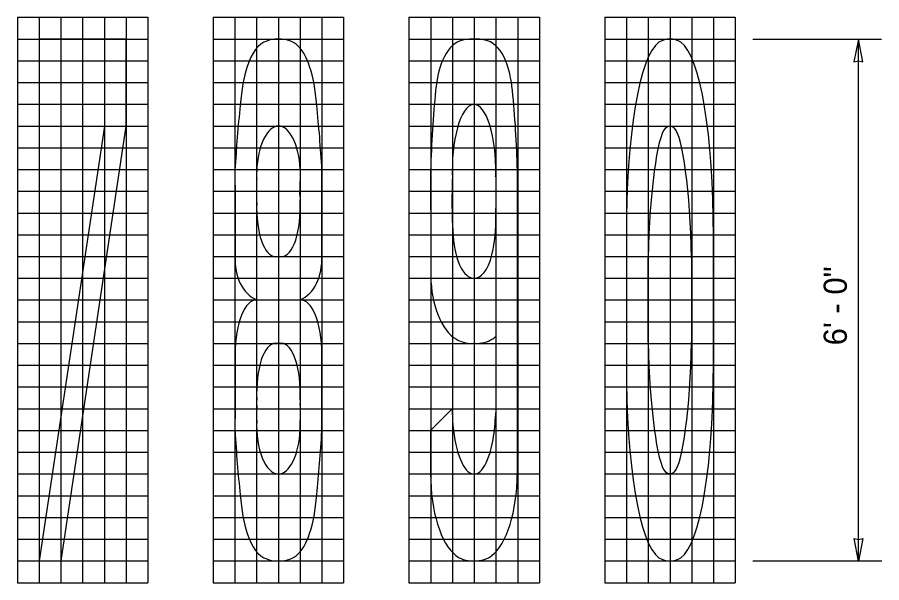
# Model space of a CAD drawing. Extents: x 99862 to 103151, y 100000 to 102076.
# Drawn here: x 101855 to 102451, y 101067 to 101457 of the extents above; entities that cross this region are included whole.
import ezdxf

# ---------------------------------------------------------------- set-up
doc = ezdxf.new("R2010")
doc.units = 0
for name, color, linetype in [('Level 15', 7, 'Continuous'), ('Level 20', 7, 'Continuous'), ('Level 4', 7, 'Continuous')]:
    doc.layers.add(name, color=color, linetype=linetype)

msp = doc.modelspace()

# ---------------------------------------------------------------- linework, layer by layer
at = {"layer": 'Level 15'}
for p, q in [((102362.5, 101442.28), (102451.43, 101442.28)), ((102435.43, 101082.28), (102435.43, 101442.28)), ((102362.5, 101082.28), (102451.46, 101082.28))]:
    msp.add_line(p, q, dxfattribs=at)
for points in [[(102435.43, 101442.28), (102432.35, 101426.55), (102435.43, 101427.28), (102438.52, 101426.55)], [(102435.46, 101082.12), (102432.38, 101097.85), (102435.46, 101097.12), (102438.55, 101097.85)]]:
    msp.add_lwpolyline(points, close=True, dxfattribs=at)
at = {"layer": 'Level 20'}
for p, q in [((102005.46, 101351.81), (102005.5, 101331.29)), ((102050.46, 101352.28), (102050.46, 101344.31)), ((102065.43, 101331.29), (102065.46, 101351.81)), ((102140.36, 101348.93), (102140.45, 101299.33)), ((102200.24, 101299.3), (102200.33, 101348.91)), ((102020.46, 101331.29), (102020.46, 101345.72)), ((102155.35, 101325.6), (102155.43, 101345.79)), ((102185.25, 101347.34), (102185.34, 101325.57)), ((102005.5, 101331.29), (102005.5, 101293.05)), ((102020.46, 101330.28), (102020.46, 101331.29)), ((102050.22, 101335.02), (102050.43, 101331.29)), ((102065.43, 101293.05), (102065.43, 101331.29)), ((102020.44, 101329.48), (102020.46, 101330.28)), ((102275.41, 101306.34), (102275.41, 101262.28)), ((102335.39, 101262.28), (102335.39, 101306.34)), ((102140.45, 101299.33), (102140.45, 101278.91)), ((102200.24, 101294.14), (102200.24, 101299.3)), ((102037.47, 101292.12), (102033.46, 101292.12)), ((102200.3, 101184.46), (102200.3, 101294.14)), ((102290.4, 101262.28), (102290.4, 101291.34)), ((102320.4, 101291.34), (102320.4, 101262.28)), ((102140.45, 101278.91), (102140.54, 101278.91)), ((102275.41, 101262.28), (102275.41, 101218.22)), ((102290.4, 101233.22), (102290.4, 101262.28)), ((102320.4, 101262.28), (102320.4, 101233.22)), ((102335.39, 101218.22), (102335.39, 101262.28)), ((102185.31, 101237.11), (102185.31, 101184.46)), ((102033.52, 101232.43), (102037.41, 101232.43)), ((102169.57, 101232.28), (102170.34, 101232.25)), ((102005.5, 101224.97), (102005.5, 101188.14)), ((102065.43, 101188.14), (102065.43, 101224.97)), ((102005.5, 101188.14), (102005.46, 101172.75)), ((102020.55, 101189.65), (102020.54, 101193.26)), ((102050.39, 101193.26), (102050.41, 101190.82)), ((102050.46, 101189.69), (102050.46, 101179.31)), ((102065.46, 101172.75), (102065.43, 101188.14)), ((102155.4, 101187.55), (102140.33, 101172.24)), ((102155.39, 101182.98), (102155.4, 101187.55)), ((102200.21, 101142.25), (102200.3, 101184.46)), ((102140.33, 101172.24), (102140.33, 101142.25)), ((102200.12, 101142.25), (102200.21, 101142.25))]:
    msp.add_line(p, q, dxfattribs=at)
msp.add_lwpolyline([(101915.46, 101382.28), (101870.46, 101082.28), (101885.7, 101082.28), (101930.46, 101382.28), (101930.46, 101442.28), (101870.46, 101442.28), (101870.46, 101382.28)], close=True, dxfattribs=at)
for centre, major_axis, ratio, start_param, end_param in [((102066.79, 101259.75), (38.58, -181.34), 0.246365, 3.159715, 3.546722), ((102035.44, 101438.76), (10.08, 0), 0.348837, 0.665473, 2.491733), ((102004.14, 101259.75), (-38.58, -181.34), 0.246365, 2.736464, 3.126953), ((102201.49, 101299.74), (-40.06, 141.44), 0.306224, 0.010044, 0.37097), ((102168.95, 101439.49), (9.69, 0.05), 0.28716, 1.501343, 2.532224), ((102169.66, 101441.83), (1.56, 0.01), 0.28716, 1.115415, 1.600803), ((102171.73, 101439.47), (-9.69, 0.05), 0.28716, 3.750961, 4.857802), ((102139.2, 101299.72), (40.06, 141.44), 0.306224, 5.912215, 6.273141), ((102305.4, 101291.97), (3.75, -149.37), 0.19927, 3.270148, 4.611013), ((102297.9, 101126.7), (-7.85, -315.58), 0.19927, 3.02647, 3.266464), ((102305.41, 101292.04), (-3.72, -149.3), 0.19927, 1.671693, 3.012646), ((102161.46, 101371.64), (-5.85, 62.71), 0.27885, 0.460005, 0.951871), ((102179.23, 101371.62), (5.85, 62.71), 0.27885, 5.331315, 5.82318), ((102026.74, 101351.71), (5.67, -80.23), 0.218823, 3.612153, 4.104018), ((102044.18, 101351.71), (-5.67, -80.23), 0.218823, 2.179168, 2.671033), ((102219.18, 101269.61), (-18.14, 275.54), 0.279295, 1.03178, 1.251054), ((102121.51, 101269.59), (18.14, 275.54), 0.279295, 5.032131, 5.251405), ((102059.93, 101269.6), (4.68, -255.82), 0.218821, 4.189125, 4.381242), ((102011, 101269.6), (-4.68, -255.82), 0.218821, 1.901943, 2.09406), ((102170.31, 101351.32), (0, 45.93), 0.326391, 0.046211, 1.691605), ((102170.31, 101351.32), (0, 45.93), 0.326391, 0.017819, 0.046211), ((102170.31, 101351.32), (0, 45.93), 0.326391, 6.281207, 6.301005), ((102170.31, 101351.32), (0, 45.93), 0.326391, 4.6597, 6.281207), ((102035.18, 101349.01), (-0.3, -33.27), 0.443662, 3.159722, 4.650111), ((102035.45, 101340.56), (0, -41.72), 0.353933, 3.140679, 3.157785), ((102035.54, 101348.41), (0.06, -33.87), 0.443662, 1.684508, 3.142616), ((102301.42, 101291.09), (-2.11, -90.25), 0.122012, 3.268533, 4.71248), ((102299.43, 101121.68), (-6.09, -260.36), 0.122012, 3.042541, 3.248082), ((102309.39, 101291.09), (2.11, -90.25), 0.122012, 1.570705, 3.018849), ((102035.18, 101349.01), (-0.3, -33.27), 0.443662, 4.650111, 4.815474), ((102219.18, 101269.61), (-18.14, 275.54), 0.279295, 1.251054, 1.260463), ((102170.31, 101351.32), (0, 45.93), 0.326391, 4.625574, 4.6597), ((102121.51, 101269.59), (18.14, 275.54), 0.279295, 5.022722, 5.032131), ((102035.33, 101340.21), (-1.08, -42.68), 0.353933, 1.608151, 1.675965), ((102035.33, 101340.21), (-1.08, -42.68), 0.353933, 1.457775, 1.608151), ((102035.57, 101331.52), (2.12, -39.39), 0.375885, 6.268799, 7.827952), ((102035.36, 101331.52), (-2.12, -39.39), 0.375885, 4.784318, 6.297572), ((102160.18, 101320.84), (0, 29.96), 0.163293, 1.411316, 2.46776), ((102180.48, 101320.83), (0, 30.12), 0.163293, 3.821205, 4.870391), ((102170.31, 101310.08), (0, 32.81), 0.435527, 1.966446, 2.78592), ((102168.83, 101314.13), (-1.69, 36.88), 0.428388, 3.209517, 4.22215), ((102115.99, 101384.93), (-100.67, -119.36), 0.381725, 5.846217, 6.385455), ((101954.94, 101384.93), (100.67, -119.36), 0.381725, 6.180916, 6.720154), ((102165.73, 101279.3), (-0.06, 46.28), 0.544273, 1.578428, 2.834125), ((102170.31, 101310.08), (0, 32.81), 0.435527, 2.78592, 3.084732), ((102170.31, 101310.08), (0, 32.81), 0.435527, 3.084732, 3.124945), ((102170.31, 101310.08), (0, 32.81), 0.435527, 3.124945, 3.145709), ((102170.19, 101321.15), (0, 43.89), 0.435527, 3.151101, 3.215129), ((102020.28, 101223.77), (0.28, -38.53), 0.383378, 3.107477, 4.678273), ((102050.65, 101223.77), (-0.28, -38.53), 0.383378, 1.604912, 3.175708), ((102174.96, 101279.27), (0.06, 46.28), 0.544273, 3.44906, 3.567316), ((102035.39, 101193.04), (2.12, -39.39), 0.375885, 3.124969, 4.686367), ((102035.54, 101193.04), (-2.12, -39.39), 0.375885, 1.596818, 3.158216), ((102170.33, 101238.02), (-14.05, 0.04), 0.409613, 0.523879, 1.517527), ((102170.36, 101238), (14.05, 0.04), 0.409613, 4.710427, 5.759306), ((102301.42, 101233.47), (2.11, -90.25), 0.122012, 4.712298, 6.156245), ((102309.39, 101233.47), (-2.11, -90.25), 0.122012, 0.122744, 1.570888), ((102305.4, 101232.59), (-3.75, -149.37), 0.19927, 4.813765, 6.15463), ((102305.41, 101232.52), (3.72, -149.3), 0.19927, 0.128946, 1.4699), ((102035.48, 101183.88), (-0.25, -42.65), 0.353933, 4.597839, 4.832837), ((102035.48, 101183.88), (-0.25, -42.65), 0.353933, 4.58824, 4.597839), ((102035.48, 101183.88), (-0.25, -42.65), 0.353933, 4.578654, 4.58824), ((102035.48, 101183.88), (-0.25, -42.65), 0.353933, 1.709628, 1.736462), ((102170.31, 101187.24), (0, 45), 0.33319, 1.665564, 4.222129), ((102058.23, 101186.69), (16.39, 144.14), 0.87517, 4.668647, 4.789722), ((102058.23, 101186.69), (16.39, 144.14), 0.87517, 4.789722, 4.796182), ((102035.17, 101175.55), (0.29, -33.27), 0.443662, 4.609304, 6.265056), ((102035.82, 101175.43), (-0.36, -33.15), 0.443662, 1.497439, 1.693033), ((102059.37, 101253.65), (-4.57, -253.18), 0.218821, 5.041601, 5.044505), ((102059.37, 101253.65), (-4.57, -253.18), 0.218821, 5.044505, 5.235652), ((102035.82, 101175.43), (-0.36, -33.15), 0.443662, 6.282162, 7.780625), ((102011.56, 101253.65), (4.57, -253.18), 0.218821, 1.047533, 1.23868), ((102011.56, 101253.65), (4.57, -253.18), 0.218821, 1.23868, 1.241584), ((102035.44, 101184), (0, -41.72), 0.353933, 6.266993, 6.284099), ((102165.63, 101142.66), (0, 59.47), 0.42542, 1.577801, 2.825639), ((102174.93, 101142.74), (0.05, 59.5), 0.423324, 3.448728, 4.704425), ((102299.43, 101402.88), (6.09, -260.36), 0.122012, 6.176696, 6.382237), ((102026.74, 101172.84), (-5.67, -80.23), 0.218823, 5.32076, 5.812625), ((102044.18, 101172.84), (5.67, -80.23), 0.218823, 0.47056, 0.962425), ((102066.79, 101264.81), (-38.58, -181.34), 0.246365, 5.878056, 6.265063), ((102004.14, 101264.81), (38.58, -181.34), 0.246365, 0.014639, 0.405129), ((102035.44, 101085.79), (10.08, 0), 0.348837, 3.791452, 5.617712), ((102170.2, 101089.76), (14.21, 0), 0.526645, 3.647253, 5.759318), ((102297.9, 101397.86), (7.85, -315.58), 0.19927, 6.158314, 6.398307)]:
    msp.add_ellipse(centre, major_axis=major_axis, ratio=ratio, start_param=start_param, end_param=end_param, dxfattribs=at)
at = {"layer": 'Level 4'}
for p, q in [((101855.43, 101457.28), (101855.43, 101067.28)), ((101855.51, 101457.28), (101945.43, 101457.28)), ((101870.43, 101457.28), (101870.43, 101067.28)), ((101885.43, 101457.28), (101885.43, 101067.28)), ((101900.43, 101457.28), (101900.43, 101067.28)), ((101915.43, 101457.28), (101915.43, 101067.28)), ((101930.43, 101457.28), (101930.43, 101067.28)), ((101945.43, 101457.28), (101945.43, 101067.28)), ((101990.43, 101457.28), (101990.43, 101067.28)), ((101990.45, 101457.28), (102080.43, 101457.28)), ((102005.43, 101457.28), (102005.43, 101067.28)), ((102020.43, 101457.28), (102020.43, 101067.28)), ((102035.43, 101457.28), (102035.43, 101067.28)), ((102050.43, 101457.28), (102050.43, 101067.28)), ((102065.43, 101457.28), (102065.43, 101067.28)), ((102080.43, 101457.28), (102080.43, 101067.28)), ((102125.43, 101457.28), (102125.43, 101067.28)), ((102125.48, 101457.28), (102215.43, 101457.28)), ((102140.43, 101457.28), (102140.43, 101067.28)), ((102155.43, 101457.28), (102155.43, 101067.28)), ((102170.43, 101457.28), (102170.43, 101067.28)), ((102185.43, 101457.28), (102185.43, 101067.28)), ((102200.43, 101457.28), (102200.43, 101067.28)), ((102215.43, 101457.28), (102215.43, 101067.28)), ((102260.49, 101457.28), (102350.5, 101457.28)), ((102260.5, 101457.28), (102260.5, 101067.28)), ((102275.5, 101457.28), (102275.5, 101067.28)), ((102290.5, 101457.28), (102290.5, 101067.28)), ((102305.5, 101457.28), (102305.5, 101067.28)), ((102320.5, 101457.28), (102320.5, 101067.28)), ((102335.5, 101457.28), (102335.5, 101067.28)), ((102350.5, 101457.28), (102350.5, 101067.28)), ((101855.36, 101442.28), (101945.43, 101442.28)), ((101990.36, 101442.28), (102080.43, 101442.28)), ((102125.36, 101442.28), (102215.43, 101442.28)), ((102260.43, 101442.28), (102350.5, 101442.28)), ((101855.36, 101427.28), (101945.43, 101427.28)), ((101990.36, 101427.28), (102080.43, 101427.28)), ((102125.36, 101427.28), (102215.43, 101427.28)), ((102260.43, 101427.28), (102350.5, 101427.28)), ((101855.57, 101412.28), (101945.43, 101412.28)), ((101990.57, 101412.28), (102080.43, 101412.28)), ((102125.57, 101412.28), (102215.43, 101412.28)), ((102260.64, 101412.28), (102350.5, 101412.28)), ((101855.36, 101397.28), (101945.43, 101397.28)), ((101990.36, 101397.28), (102080.43, 101397.28)), ((102125.36, 101397.28), (102215.43, 101397.28)), ((102260.43, 101397.28), (102350.5, 101397.28)), ((101855.36, 101382.28), (101945.43, 101382.28)), ((101990.36, 101382.28), (102080.43, 101382.28)), ((102125.36, 101382.28), (102215.43, 101382.28)), ((102260.43, 101382.28), (102350.5, 101382.28)), ((101855.47, 101367.28), (101945.43, 101367.28)), ((101990.47, 101367.28), (102080.43, 101367.28)), ((102125.47, 101367.28), (102215.43, 101367.28)), ((102260.54, 101367.28), (102350.5, 101367.28)), ((101855.47, 101352.28), (101945.43, 101352.28)), ((101990.47, 101352.28), (102080.43, 101352.28)), ((102125.47, 101352.28), (102215.43, 101352.28)), ((102260.54, 101352.28), (102350.5, 101352.28)), ((101855.57, 101337.28), (101945.43, 101337.28)), ((101990.57, 101337.28), (102080.43, 101337.28)), ((102125.57, 101337.28), (102215.43, 101337.28)), ((102260.64, 101337.28), (102350.5, 101337.28)), ((101855.57, 101322.28), (101945.43, 101322.28)), ((101990.57, 101322.28), (102080.43, 101322.28)), ((102125.57, 101322.28), (102215.43, 101322.28)), ((102260.64, 101322.28), (102350.5, 101322.28)), ((101855.36, 101307.28), (101945.43, 101307.28)), ((101990.36, 101307.28), (102080.43, 101307.28)), ((102125.36, 101307.28), (102215.43, 101307.28)), ((102260.43, 101307.28), (102350.5, 101307.28)), ((101855.47, 101292.28), (101945.43, 101292.28)), ((101990.47, 101292.28), (102080.43, 101292.28)), ((102125.47, 101292.28), (102215.43, 101292.28)), ((102260.54, 101292.28), (102350.5, 101292.28)), ((101855.36, 101277.28), (101945.43, 101277.28)), ((101990.36, 101277.28), (102080.43, 101277.28)), ((102125.36, 101277.28), (102215.43, 101277.28)), ((102260.43, 101277.28), (102350.5, 101277.28)), ((101855.47, 101262.28), (101945.43, 101262.28)), ((101990.47, 101262.28), (102080.43, 101262.28)), ((102125.47, 101262.28), (102215.43, 101262.28)), ((102260.54, 101262.28), (102350.5, 101262.28)), ((101855.47, 101247.28), (101945.43, 101247.28)), ((101990.47, 101247.28), (102080.43, 101247.28)), ((102125.47, 101247.28), (102215.43, 101247.28)), ((102260.54, 101247.28), (102350.5, 101247.28)), ((101855.36, 101232.28), (101945.43, 101232.28)), ((101990.36, 101232.28), (102080.43, 101232.28)), ((102125.36, 101232.28), (102215.43, 101232.28)), ((102260.43, 101232.28), (102350.5, 101232.28)), ((101855.47, 101217.28), (101945.43, 101217.28)), ((101990.47, 101217.28), (102080.43, 101217.28)), ((102125.47, 101217.28), (102215.43, 101217.28)), ((102260.54, 101217.28), (102350.5, 101217.28)), ((101855.47, 101202.28), (101945.43, 101202.28)), ((101990.47, 101202.28), (102080.43, 101202.28)), ((102125.47, 101202.28), (102215.43, 101202.28)), ((102260.54, 101202.28), (102350.5, 101202.28)), ((101855.47, 101187.28), (101945.43, 101187.28)), ((101990.47, 101187.28), (102080.43, 101187.28)), ((102125.47, 101187.28), (102215.43, 101187.28)), ((102260.54, 101187.28), (102350.5, 101187.28)), ((101855.47, 101172.28), (101945.43, 101172.28)), ((101990.47, 101172.28), (102080.43, 101172.28)), ((102125.47, 101172.28), (102215.43, 101172.28)), ((102260.54, 101172.28), (102350.5, 101172.28)), ((101855.47, 101157.28), (101945.43, 101157.28)), ((101990.47, 101157.28), (102080.43, 101157.28)), ((102125.47, 101157.28), (102215.43, 101157.28)), ((102260.54, 101157.28), (102350.5, 101157.28)), ((101855.57, 101142.28), (101945.43, 101142.28)), ((101990.57, 101142.28), (102080.43, 101142.28)), ((102125.57, 101142.28), (102215.43, 101142.28)), ((102260.64, 101142.28), (102350.5, 101142.28)), ((101855.47, 101127.28), (101945.43, 101127.28)), ((101990.47, 101127.28), (102080.43, 101127.28)), ((102125.47, 101127.28), (102215.43, 101127.28)), ((102260.54, 101127.28), (102350.5, 101127.28)), ((101855.47, 101112.28), (101945.43, 101112.28)), ((101990.47, 101112.28), (102080.43, 101112.28)), ((102125.47, 101112.28), (102215.43, 101112.28)), ((102260.54, 101112.28), (102350.5, 101112.28)), ((101855.47, 101097.28), (101945.43, 101097.28)), ((101990.47, 101097.28), (102080.43, 101097.28)), ((102125.47, 101097.28), (102215.43, 101097.28)), ((102260.54, 101097.28), (102350.5, 101097.28)), ((101855.36, 101082.28), (101945.43, 101082.28)), ((101990.36, 101082.28), (102080.43, 101082.28)), ((102125.36, 101082.28), (102215.43, 101082.28)), ((102260.43, 101082.28), (102350.5, 101082.28)), ((101855.47, 101067.28), (101945.43, 101067.28)), ((101990.47, 101067.28), (102080.43, 101067.28)), ((102125.47, 101067.28), (102215.43, 101067.28)), ((102260.54, 101067.28), (102350.5, 101067.28))]:
    msp.add_line(p, q, dxfattribs=at)

# ---------------------------------------------------------------- texts
at = {"layer": 'Level 20'}
msp.add_text('6\' - 0" ', height=16, rotation=90, dxfattribs=at).set_placement((102427.43, 101230.99))

doc.saveas('drawing.dxf')
